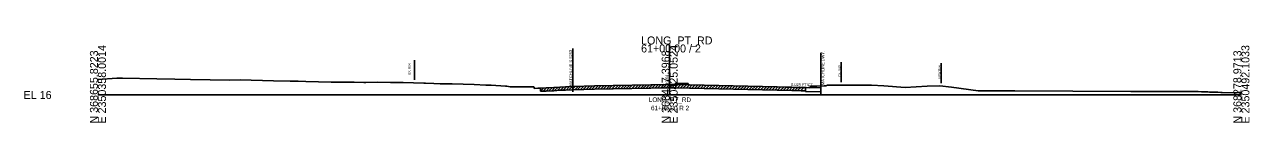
# Model space of a CAD drawing. Extents: x 974 to 2350744, y -10 to 368509.
# Drawn here: x 1974.3 to 2402.8, y 5490.3 to 5520.5 of the extents above; entities that cross this region are included whole.
import ezdxf

# ---------------------------------------------------------------- set-up
doc = ezdxf.new("R2010")
doc.units = 0
for name, color, linetype in [('RD_GPK_XS_Cell', 7, 'Continuous'), ('RD_PD_ConcMed', 7, 'Continuous'), ('RD_XS_Base', 7, 'Continuous'), ('RD_XS_ExGround', 7, 'Continuous'), ('RD_XS_ExPaveRet', 7, 'Continuous'), ('RD_XS_ExRW', 7, 'Continuous'), ('RD_XS_MatchLine', 7, 'Continuous'), ('RD_XS_NewRW', 7, 'Continuous'), ('RD_XS_Pave', 7, 'Continuous'), ('RD_XS_TX_Elev_EX', 7, 'Continuous'), ('RD_XS_TX_Slope', 7, 'Continuous'), ('RD_XS_TX_Station', 7, 'Continuous')]:
    doc.layers.add(name, color=color, linetype=linetype)

msp = doc.modelspace()

# ---------------------------------------------------------------- linework, layer by layer
at = {"layer": 'RD_GPK_XS_Cell'}
for p, q in [((2200, 5500), (2200, 5517.7)), ((2000, 5500), (2200, 5500)), ((2200, 5500), (2400, 5500))]:
    msp.add_line(p, q, dxfattribs=at)
at = {"layer": 'RD_PD_ConcMed'}
for p, q in [((2202, 5503.67), (2202, 5504.17)), ((2202, 5504.17), (2206.53, 5504.06)), ((2206.53, 5503.56), (2206.53, 5504.06))]:
    msp.add_line(p, q, dxfattribs=at)
at = {"layer": 'RD_XS_Base'}
for p, q in [((2247.48, 5501.24), (2247.48, 5502.58)), ((2252.87, 5501.11), (2252.87, 5502.45)), ((2247.48, 5501.24), (2252.87, 5501.11))]:
    msp.add_line(p, q, dxfattribs=at)
at = {"layer": 'RD_XS_ExGround'}
msp.add_lwpolyline([(2000, 5505.39), (2006.63, 5505.88), (2007.48, 5505.9), (2007.83, 5505.9), (2008.58, 5505.89), (2020.65, 5505.61), (2026.84, 5505.51), (2032.4, 5505.43), (2046.18, 5505.23), (2049.74, 5505.25), (2061.38, 5504.98), (2067.28, 5504.79), (2068.07, 5504.82), (2070.05, 5504.8), (2072.67, 5504.72), (2081.53, 5504.49), (2089.61, 5504.5), (2093.03, 5504.42), (2093.74, 5504.41), (2097.89, 5504.44), (2102.36, 5504.36), (2106.77, 5504.37), (2114.02, 5504.16), (2114.6, 5504.14), (2117.48, 5504.07), (2119.77, 5503.89), (2123.92, 5503.9), (2131.56, 5503.72), (2135.64, 5503.48), (2137.56, 5503.39), (2142.61, 5503.14), (2142.95, 5503.1), (2144.3, 5502.8), (2151.7, 5502.8), (2151.78, 5502.8), (2152.47, 5502.81), (2152.69, 5502.32), (2153.84, 5502.38), (2154.77, 5502.42), (2156.79, 5502.51), (2159.52, 5502.66), (2161.54, 5502.79), (2163.54, 5502.85), (2166.39, 5503), (2173.68, 5503.16), (2200, 5503.64), (2201.77, 5503.68), (2242.73, 5502.7), (2243.97, 5502.68), (2245.95, 5502.64), (2247.48, 5502.62), (2249.05, 5502.54), (2249.22, 5503.04), (2249.75, 5503.04), (2250.24, 5503.05), (2251.53, 5503.1), (2254.09, 5503.18), (2254.59, 5503.19), (2255.27, 5503.43), (2256.46, 5503.49), (2261.67, 5503.46), (2264.23, 5503.43), (2266.3, 5503.46), (2270.62, 5503.4), (2274.89, 5503.17), (2282.35, 5502.62), (2290.09, 5503.08), (2294.55, 5503.22), (2298.6, 5502.76), (2307.96, 5501.4), (2312.49, 5501.48), (2315.38, 5501.4), (2320.75, 5501.49), (2361.36, 5501.25), (2384.89, 5501.19), (2386.05, 5501.13), (2386.65, 5501.11), (2387.05, 5501.09), (2387.74, 5501.08), (2388.23, 5501.05), (2388.85, 5500.99), (2391.76, 5500.94), (2392.86, 5500.92), (2393.23, 5500.92), (2397.61, 5500.77), (2398.25, 5500.81), (2398.78, 5500.83), (2399.2, 5500.83), (2399.68, 5500.82), (2400, 5500.81)], dxfattribs=at)
at = {"layer": 'RD_XS_ExPaveRet'}
for p, q in [((2154.77, 5501.28), (2155.96, 5502.48)), ((2154.77, 5501.28), (2154.77, 5502.42)), ((2155.77, 5501.32), (2156.97, 5502.52)), ((2156.77, 5501.37), (2157.98, 5502.57)), ((2157.77, 5501.42), (2158.98, 5502.63)), ((2158.77, 5501.47), (2159.98, 5502.69)), ((2159.77, 5501.53), (2160.99, 5502.75)), ((2160.77, 5501.59), (2161.98, 5502.8)), ((2161.77, 5501.65), (2162.95, 5502.83)), ((2162.77, 5501.68), (2163.96, 5502.87)), ((2163.77, 5501.72), (2164.98, 5502.93)), ((2164.77, 5501.77), (2165.98, 5502.98)), ((2165.77, 5501.82), (2166.96, 5503.01)), ((2166.77, 5501.86), (2167.94, 5503.03)), ((2167.77, 5501.88), (2168.94, 5503.05)), ((2168.77, 5501.91), (2169.94, 5503.08)), ((2169.77, 5501.93), (2170.94, 5503.1)), ((2170.77, 5501.95), (2171.94, 5503.12)), ((2171.77, 5501.97), (2172.94, 5503.14)), ((2172.77, 5501.99), (2173.94, 5503.16)), ((2173.68, 5502.01), (2200, 5502.5)), ((2173.77, 5502.02), (2174.94, 5503.18)), ((2174.77, 5502.03), (2175.94, 5503.2)), ((2175.77, 5502.05), (2176.94, 5503.22)), ((2176.77, 5502.07), (2177.94, 5503.24)), ((2177.77, 5502.09), (2178.94, 5503.25)), ((2178.77, 5502.11), (2179.94, 5503.27)), ((2179.77, 5502.13), (2180.94, 5503.29)), ((2180.77, 5502.15), (2181.94, 5503.31)), ((2181.77, 5502.16), (2182.94, 5503.33)), ((2182.77, 5502.18), (2183.94, 5503.35)), ((2183.77, 5502.2), (2184.94, 5503.37)), ((2184.77, 5502.22), (2185.94, 5503.38)), ((2185.77, 5502.24), (2186.94, 5503.4)), ((2186.77, 5502.26), (2187.94, 5503.42)), ((2187.77, 5502.27), (2188.94, 5503.44)), ((2188.77, 5502.29), (2189.94, 5503.46)), ((2189.77, 5502.31), (2190.94, 5503.48)), ((2190.77, 5502.33), (2191.94, 5503.49)), ((2191.77, 5502.35), (2192.94, 5503.51)), ((2192.77, 5502.37), (2193.94, 5503.53)), ((2193.77, 5502.39), (2194.94, 5503.55)), ((2194.77, 5502.4), (2195.94, 5503.57)), ((2195.77, 5502.42), (2196.94, 5503.59)), ((2196.77, 5502.44), (2197.94, 5503.61)), ((2197.77, 5502.46), (2198.94, 5503.62)), ((2198.77, 5502.48), (2199.94, 5503.64)), ((2199.77, 5502.5), (2200.94, 5503.66)), ((2200, 5502.5), (2201.77, 5502.53)), ((2200.77, 5502.51), (2201.93, 5503.67)), ((2201.77, 5502.53), (2202.89, 5503.65)), ((2201.77, 5502.53), (2242.73, 5501.56)), ((2202.77, 5502.51), (2203.89, 5503.63)), ((2203.77, 5502.49), (2204.89, 5503.6)), ((2204.77, 5502.46), (2205.89, 5503.58)), ((2205.77, 5502.44), (2206.89, 5503.55)), ((2206.77, 5502.41), (2207.89, 5503.53)), ((2207.77, 5502.39), (2208.89, 5503.51)), ((2208.77, 5502.37), (2209.89, 5503.48)), ((2209.77, 5502.34), (2210.89, 5503.46)), ((2210.77, 5502.32), (2211.89, 5503.44)), ((2211.77, 5502.3), (2212.89, 5503.41)), ((2212.77, 5502.27), (2213.89, 5503.39)), ((2213.77, 5502.25), (2214.89, 5503.37)), ((2214.77, 5502.22), (2215.89, 5503.34)), ((2215.77, 5502.2), (2216.89, 5503.32)), ((2216.77, 5502.18), (2217.89, 5503.29)), ((2217.77, 5502.15), (2218.89, 5503.27)), ((2218.77, 5502.13), (2219.89, 5503.25)), ((2219.77, 5502.11), (2220.89, 5503.22)), ((2220.77, 5502.08), (2221.89, 5503.2)), ((2221.77, 5502.06), (2222.89, 5503.18)), ((2222.77, 5502.03), (2223.89, 5503.15)), ((2223.77, 5502.01), (2224.89, 5503.13)), ((2224.77, 5501.99), (2225.89, 5503.1)), ((2225.77, 5501.96), (2226.89, 5503.08)), ((2226.77, 5501.94), (2227.89, 5503.06)), ((2227.77, 5501.92), (2228.89, 5503.03)), ((2228.77, 5501.89), (2229.89, 5503.01)), ((2229.77, 5501.87), (2230.89, 5502.99)), ((2230.77, 5501.84), (2231.89, 5502.96)), ((2231.77, 5501.82), (2232.89, 5502.94)), ((2232.77, 5501.8), (2233.89, 5502.91)), ((2233.77, 5501.77), (2234.89, 5502.89)), ((2234.77, 5501.75), (2235.89, 5502.87)), ((2235.77, 5501.73), (2236.89, 5502.84)), ((2236.77, 5501.7), (2237.89, 5502.82)), ((2237.77, 5501.68), (2238.89, 5502.8)), ((2238.77, 5501.66), (2239.89, 5502.77)), ((2239.77, 5501.63), (2240.89, 5502.75)), ((2240.77, 5501.61), (2241.89, 5502.72)), ((2241.77, 5501.58), (2242.89, 5502.7)), ((2242.77, 5501.56), (2243.9, 5502.69)), ((2243.77, 5501.54), (2244.89, 5502.66)), ((2244.77, 5501.52), (2245.89, 5502.64)), ((2245.77, 5501.5), (2246.9, 5502.63)), ((2247.48, 5502.62), (2247.48, 5501.48)), ((2154.77, 5501.28), (2156.79, 5501.37)), ((2156.79, 5501.37), (2159.52, 5501.51)), ((2159.52, 5501.51), (2161.54, 5501.64)), ((2161.54, 5501.64), (2163.54, 5501.71)), ((2163.54, 5501.71), (2166.39, 5501.85)), ((2166.39, 5501.85), (2173.68, 5502.01)), ((2242.73, 5501.56), (2243.97, 5501.54)), ((2243.97, 5501.54), (2245.95, 5501.5)), ((2245.95, 5501.5), (2247.48, 5501.48))]:
    msp.add_line(p, q, dxfattribs=at)
at = {"layer": 'RD_XS_ExRW'}
for p, q in [((2110.77, 5505.25), (2110.77, 5512.25)), ((2260, 5504.47), (2260, 5511.47))]:
    msp.add_line(p, q, dxfattribs=at)
at = {"layer": 'RD_XS_MatchLine'}
for p, q in [((2166.13, 5516.31), (2166.13, 5501.05)), ((2252.87, 5514.74), (2252.87, 5500))]:
    msp.add_line(p, q, dxfattribs=at)
at = {"layer": 'RD_XS_NewRW'}
msp.add_line((2295, 5504.17), (2295, 5511.17), dxfattribs=at)
at = {"layer": 'RD_XS_Pave'}
msp.add_line((2241, 5502.75), (2252.87, 5502.45), dxfattribs=at)

# ---------------------------------------------------------------- texts
at = {"layer": 'RD_GPK_XS_Cell'}
for s, p in [('LONG_PT_RD', (2190, 5517.7)), ('61+00.00 / 2', (2190, 5514.9)), ('EL 16', (1974, 5498.6))]:
    msp.add_text(s, height=2.8, dxfattribs=at).set_placement(p)
for s, p in [('N 368655.8223', (2000, 5490)), ('E 2350358.0014', (2002.8, 5490)), ('N 368467.3968', (2200, 5490)), ('E 2350425.0524', (2202.8, 5490)), ('N 368278.9713', (2400, 5490)), ('E 2350492.1033', (2402.8, 5490))]:
    msp.add_text(s, height=2.8, rotation=90, dxfattribs=at).set_placement(p)
at = {"layer": 'RD_XS_ExRW'}
for p in [(2109.35, 5507.2), (2259.75, 5506.42)]:
    msp.add_text('EX. R/W ', height=0.75, rotation=90, dxfattribs=at).set_placement(p)
at = {"layer": 'RD_XS_MatchLine'}
for s, p in [('MATCHLINE S-5253', (2165.87, 5502.99)), ('MATCHLINE DWY.', (2254.09, 5503.47))]:
    msp.add_text(s, height=1, rotation=90, dxfattribs=at).set_placement(p)
at = {"layer": 'RD_XS_NewRW'}
msp.add_text('NEW R/W ', height=0.75, rotation=90, dxfattribs=at).set_placement((2294.75, 5505.76))
at = {"layer": 'RD_XS_TX_Elev_EX'}
msp.add_text('19.64', height=1, rotation=90, dxfattribs=at).set_placement((2199.51, 5503.64))
at = {"layer": 'RD_XS_TX_Slope'}
msp.add_text('0.025 FT/FT', height=1, rotation=358.5679, dxfattribs=at).set_placement((2242.42, 5503.17))
at = {"layer": 'RD_XS_TX_Station'}
for s, p in [('LONG_PT_RD', (2192.72, 5497.54)), ('61+00.00 R 2', (2193.48, 5494.64))]:
    msp.add_text(s, height=1.6, dxfattribs=at).set_placement(p)

doc.saveas('drawing.dxf')
